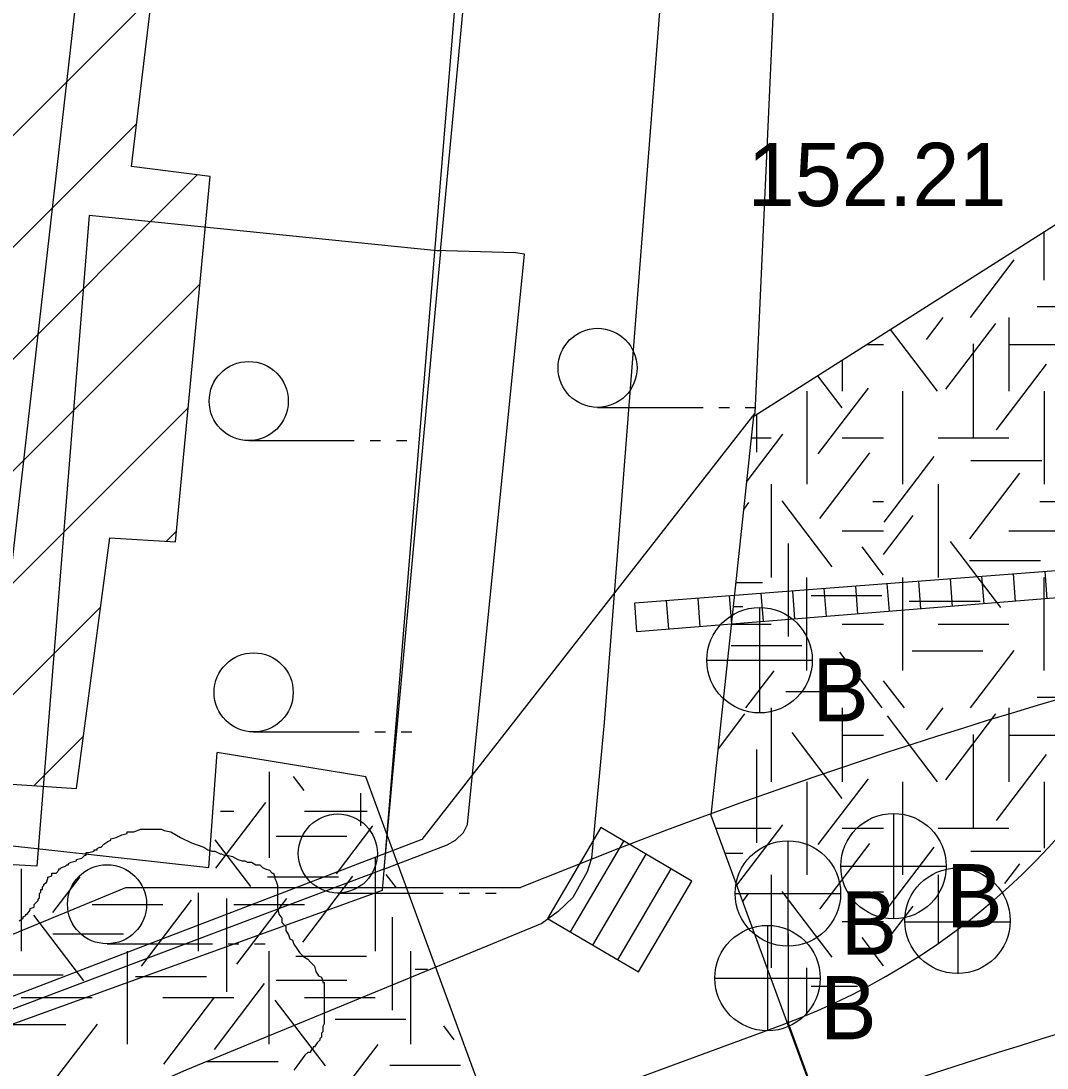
# Model space of a CAD drawing. Extents: x 419101 to 420177, y 4451541 to 4452254.
# Drawn here: x 419828.86 to 419848.32, y 4451830.95 to 4451850.82 of the extents above; entities that cross this region are included whole.
import ezdxf

# ---------------------------------------------------------------- set-up
doc = ezdxf.new("R2010")
doc.units = 0
for name, color, linetype in [('2_KADASTRO', 7, 'Continuous'), ('3_HALİHAZIR', 7, 'Continuous'), ('Level 10', 7, 'Continuous'), ('Level 3', 7, 'Continuous'), ('Level 41', 7, 'Continuous'), ('Level 60', 7, 'Continuous'), ('Level 62', 7, 'Continuous')]:
    doc.layers.add(name, color=color, linetype=linetype)

msp = doc.modelspace()

# ---------------------------------------------------------------- linework, layer by layer
at = {"layer": '2_KADASTRO'}
msp.add_lwpolyline([(419797.492, 4451855.675), (419798.065, 4451861.346), (419799.155, 4451872.13), (419838.56, 4451869.237), (419837.11, 4451851.442), (419836.727, 4451846.749), (419835.711, 4451834.324), (419821.984, 4451829.361), (419818.491, 4451828.088), (419798.137, 4451820.727)], close=True, dxfattribs=at)
at = {"layer": '3_HALİHAZIR'}
for p, q in [((419824.534, 4451844.473), (419831.34, 4451851.279)), ((419817.894, 4451835.712), (419831.054, 4451848.872)), ((419819.841, 4451835.537), (419832.201, 4451847.898)), ((419821.788, 4451835.363), (419832.255, 4451845.83)), ((419823.735, 4451835.188), (419832.033, 4451843.487)), ((419839.794, 4451843.486), (419841.794, 4451843.486)), ((419842.094, 4451843.486), (419842.294, 4451843.486)), ((419842.594, 4451843.486), (419842.794, 4451843.486)), ((419833.178, 4451842.856), (419835.178, 4451842.856)), ((419835.478, 4451842.856), (419835.678, 4451842.856)), ((419835.978, 4451842.856), (419836.178, 4451842.856)), ((419831.616, 4451840.948), (419831.811, 4451841.143)), ((419847.676, 4451840.327), (419847.716, 4451839.807)), ((419848.275, 4451840.373), (419848.314, 4451839.855)), ((419845.283, 4451840.144), (419845.324, 4451839.615)), ((419845.882, 4451840.19), (419845.922, 4451839.663)), ((419846.48, 4451840.236), (419846.52, 4451839.711)), ((419847.078, 4451840.282), (419847.118, 4451839.759)), ((419842.89, 4451839.961), (419842.932, 4451839.422)), ((419843.489, 4451840.007), (419843.53, 4451839.47)), ((419844.087, 4451840.052), (419844.128, 4451839.519)), ((419844.685, 4451840.098), (419844.726, 4451839.567)), ((419841.096, 4451839.823), (419841.137, 4451839.278)), ((419841.694, 4451839.869), (419841.736, 4451839.326)), ((419842.292, 4451839.915), (419842.334, 4451839.374)), ((419827.112, 4451836.445), (419830.37, 4451839.702)), ((419842.867, 4451839.69), (419842.867, 4451837.69)), ((419841.867, 4451838.69), (419843.867, 4451838.69)), ((419829.099, 4451836.31), (419830.041, 4451837.252)), ((419833.271, 4451837.33), (419835.271, 4451837.33)), ((419835.571, 4451837.33), (419835.771, 4451837.33)), ((419836.071, 4451837.33), (419836.271, 4451837.33)), ((419845.407, 4451835.783), (419845.407, 4451833.783)), ((419839.857, 4451835.515), (419838.844, 4451833.791)), ((419839.857, 4451835.515), (419838.844, 4451833.791)), ((419841.581, 4451834.502), (419839.857, 4451835.515)), ((419841.581, 4451834.502), (419839.857, 4451835.515)), ((419839.279, 4451833.535), (419840.292, 4451835.26)), ((419843.404, 4451835.266), (419843.404, 4451833.266)), ((419839.706, 4451833.284), (419840.719, 4451835.009)), ((419844.407, 4451834.783), (419846.407, 4451834.783)), ((419840.178, 4451833.007), (419841.192, 4451834.731)), ((419846.636, 4451832.74), (419846.636, 4451834.74)), ((419840.568, 4451832.778), (419841.581, 4451834.502)), ((419840.568, 4451832.778), (419841.581, 4451834.502)), ((419834.868, 4451834.274), (419836.868, 4451834.274)), ((419837.168, 4451834.274), (419837.368, 4451834.274)), ((419837.668, 4451834.274), (419837.868, 4451834.274)), ((419842.404, 4451834.266), (419844.404, 4451834.266)), ((419838.844, 4451833.791), (419840.568, 4451832.778)), ((419838.844, 4451833.791), (419840.568, 4451832.778)), ((419843.017, 4451833.661), (419843.017, 4451831.661)), ((419845.616, 4451833.73), (419847.616, 4451833.73)), ((419830.49, 4451833.311), (419832.49, 4451833.311)), ((419832.79, 4451833.311), (419832.99, 4451833.311)), ((419833.29, 4451833.311), (419833.49, 4451833.311)), ((419842.017, 4451832.661), (419844.017, 4451832.661))]:
    msp.add_line(p, q, dxfattribs=at)
for points in [[(419803.705, 4451853.541), (419803.094, 4451846.379), (419801.617, 4451846.462), (419800.912, 4451838.831), (419802.392, 4451838.591), (419801.958, 4451833.65), (419805.823, 4451833.166), (419805.704, 4451831.876), (419812.088, 4451831.235), (419812.306, 4451832.66), (419816.19, 4451832.424), (419816.618, 4451837.226), (419817.403, 4451837.21), (419817.369, 4451835.759), (419825.037, 4451835.071), (419825.286, 4451836.569), (419829.908, 4451836.255), (419830.545, 4451841.011), (419831.791, 4451840.938), (419832.448, 4451847.867), (419830.957, 4451848.053), (419831.347, 4451851.339)], [(419836.817, 4451846.452), (419837.348, 4451852.133)], [(419841.024, 4451851.727), (419839.922, 4451837.507), (419839.676, 4451834.933), (419839.599, 4451834.673), (419839.324, 4451834.19), (419839.045, 4451833.925), (419838.738, 4451833.693), (419831.983, 4451830.915), (419822.667, 4451826.822)], [(419836.817, 4451846.452), (419830.148, 4451847.127), (419829.16, 4451834.781), (419822.436, 4451835.166), (419822.134, 4451829.599)], [(419836.817, 4451846.452), (419835.738, 4451834.729), (419822.093, 4451829.583)], [(419835.738, 4451834.729), (419836.944, 4451835.189), (419837.098, 4451835.277), (419837.254, 4451835.42), (419837.327, 4451835.573), (419838.41, 4451846.393), (419838.237, 4451846.42), (419836.693, 4451846.465)]]:
    msp.add_lwpolyline(points, dxfattribs=at)
msp.add_lwpolyline([(419840.539, 4451839.23), (419840.498, 4451839.777), (419851.208, 4451840.598), (419851.255, 4451840.092)], close=True, dxfattribs=at)
for centre, radius in [((419839.794, 4451844.236), 0.75), ((419833.178, 4451843.606), 0.75), ((419842.867, 4451838.69), 1), ((419833.271, 4451838.08), 0.75), ((419834.868, 4451835.024), 0.75), ((419845.407, 4451834.783), 1), ((419843.404, 4451834.266), 1), ((419830.49, 4451834.061), 0.75), ((419846.621, 4451833.748), 1), ((419843.017, 4451832.661), 1)]:
    msp.add_circle(centre, radius, dxfattribs=at)
at = {"layer": 'Level 10'}
msp.add_lwpolyline([(419794.315, 4451890.489), (419840.672, 4451887.325), (419843.481, 4451858.847), (419842.779, 4451843.378), (419836.458, 4451835.291), (419798.881, 4451820.877), (419792.208, 4451851.112), (419791.857, 4451872.559)], close=True, dxfattribs=at)
at = {"layer": 'Level 3'}
for points in [[(419830.664, 4451835.328), (419830.768, 4451835.38), (419830.871, 4451835.406), (419830.871, 4451835.432), (419830.897, 4451835.432), (419830.923, 4451835.432), (419831.001, 4451835.432), (419831.131, 4451835.484), (419831.235, 4451835.484), (419831.312, 4451835.484), (419831.364, 4451835.484), (419831.442, 4451835.484), (419831.494, 4451835.484), (419831.52, 4451835.484), (419831.572, 4451835.458), (419831.702, 4451835.432), (419831.883, 4451835.328), (419832.091, 4451835.224), (419832.324, 4451835.146), (419832.402, 4451835.094), (419832.48, 4451835.068), (419832.532, 4451835.068), (419832.584, 4451835.042), (419832.635, 4451835.016), (419832.661, 4451835.016), (419832.713, 4451834.99), (419832.765, 4451834.99), (419832.869, 4451834.964), (419832.973, 4451834.912), (419833.05, 4451834.886), (419833.102, 4451834.886), (419833.154, 4451834.86), (419833.206, 4451834.86), (419833.232, 4451834.86), (419833.31, 4451834.809), (419833.388, 4451834.809), (419833.44, 4451834.757), (419833.491, 4451834.731), (419833.569, 4451834.705), (419833.621, 4451834.653), (419833.647, 4451834.653), (419833.673, 4451834.575), (419833.673, 4451834.549), (419833.699, 4451834.497), (419833.725, 4451834.419), (419833.725, 4451834.393), (419833.725, 4451834.315), (419833.725, 4451834.263), (419833.725, 4451834.185), (419833.725, 4451834.159), (419833.725, 4451834.081), (419833.725, 4451834.004), (419833.751, 4451833.874), (419833.803, 4451833.796), (419833.803, 4451833.718), (419833.881, 4451833.64), (419833.881, 4451833.562), (419833.932, 4451833.484), (419833.958, 4451833.406), (419834.01, 4451833.38), (419834.036, 4451833.302), (419834.088, 4451833.224), (419834.14, 4451833.147), (419834.218, 4451833.069), (419834.296, 4451833.017), (419834.347, 4451832.965), (419834.373, 4451832.939), (419834.425, 4451832.887), (419834.451, 4451832.783), (419834.503, 4451832.705), (419834.555, 4451832.679), (419834.581, 4451832.601), (419834.581, 4451832.575), (419834.607, 4451832.575), (419834.607, 4451832.549), (419834.607, 4451832.523), (419834.607, 4451832.471), (419834.607, 4451832.368), (419834.607, 4451832.316), (419834.607, 4451832.238), (419834.607, 4451832.16), (419834.607, 4451832.082), (419834.607, 4451832.004), (419834.607, 4451831.926), (419834.607, 4451831.874), (419834.607, 4451831.796), (419834.581, 4451831.744), (419834.581, 4451831.64), (419834.555, 4451831.614), (419834.555, 4451831.537), (419834.529, 4451831.511), (419834.529, 4451831.485), (419834.477, 4451831.433), (419834.425, 4451831.355), (419834.399, 4451831.355), (419834.399, 4451831.329), (419834.373, 4451831.303), (419834.347, 4451831.277), (419834.347, 4451831.251), (419834.322, 4451831.251), (419834.296, 4451831.251)], [(419828.822, 4451833.744), (419828.9, 4451833.796), (419828.9, 4451833.822), (419828.952, 4451833.848), (419828.952, 4451833.874), (419828.978, 4451833.874), (419829.03, 4451833.952), (419829.03, 4451833.978), (419829.107, 4451834.004), (419829.107, 4451834.029), (419829.107, 4451834.055), (419829.159, 4451834.107), (419829.185, 4451834.133), (419829.185, 4451834.159), (419829.211, 4451834.185), (419829.211, 4451834.211), (419829.211, 4451834.237), (419829.211, 4451834.263), (419829.237, 4451834.289), (419829.237, 4451834.315), (419829.237, 4451834.341), (419829.263, 4451834.341), (419829.263, 4451834.367), (419829.263, 4451834.393), (419829.289, 4451834.419), (419829.289, 4451834.445), (419829.341, 4451834.471), (419829.367, 4451834.549), (419829.367, 4451834.575), (419829.445, 4451834.601), (419829.445, 4451834.627), (419829.445, 4451834.653), (419829.522, 4451834.653), (419829.574, 4451834.705), (419829.574, 4451834.731), (419829.6, 4451834.731), (419829.626, 4451834.757), (419829.704, 4451834.783), (419829.73, 4451834.809), (419829.756, 4451834.809), (419829.756, 4451834.835), (419829.808, 4451834.86), (419829.912, 4451834.886), (419829.912, 4451834.912), (419830.015, 4451834.938), (419830.067, 4451834.99), (419830.093, 4451834.99), (419830.093, 4451835.016), (419830.093, 4451835.042), (419830.145, 4451835.042), (419830.249, 4451835.068), (419830.249, 4451835.094), (419830.275, 4451835.094), (419830.301, 4451835.094), (419830.301, 4451835.12), (419830.353, 4451835.146), (419830.379, 4451835.146), (419830.43, 4451835.198), (419830.508, 4451835.25), (419830.56, 4451835.276), (419830.56, 4451835.302), (419830.664, 4451835.328)], [(419834.296, 4451831.251), (419834.244, 4451831.199), (419834.088, 4451830.991), (419834.036, 4451830.913)]]:
    msp.add_lwpolyline(points, dxfattribs=at)
at = {"layer": 'Level 41'}
for p, q in [((419848.268, 4451845.902), (419848.268, 4451846.82)), ((419846.867, 4451845.193), (419847.696, 4451846.284)), ((419848.129, 4451845.399), (419849.472, 4451845.399)), ((419846.03, 4451844.776), (419846.347, 4451845.193)), ((419847.596, 4451845.193), (419847.596, 4451843.795)), ((419846.241, 4451843.795), (419845.352, 4451844.965)), ((419846.401, 4451843.83), (419847.35, 4451845.08)), ((419844.902, 4451844.679), (419845.22, 4451844.679)), ((419846.921, 4451844.691), (419846.921, 4451842.924)), ((419847.596, 4451844.679), (419848.939, 4451844.679)), ((419844.432, 4451844.38), (419844.432, 4451843.795)), ((419844.432, 4451844.38), (419844.432, 4451843.795)), ((419847.361, 4451843.058), (419848.31, 4451844.308)), ((419844.433, 4451843.479), (419843.971, 4451844.087)), ((419843.761, 4451843.795), (419843.761, 4451842.028)), ((419843.761, 4451843.795), (419843.761, 4451842.028)), ((419843.981, 4451842.602), (419844.93, 4451843.852)), ((419845.582, 4451842.028), (419845.582, 4451843.795)), ((419848.268, 4451843.795), (419848.268, 4451842.028)), ((419842.807, 4451843.346), (419842.807, 4451842.638)), ((419842.629, 4451842.087), (419843.305, 4451842.977)), ((419842.717, 4451842.911), (419843.089, 4451842.911)), ((419844.432, 4451842.911), (419845.22, 4451842.911)), ((419846.253, 4451842.911), (419847.596, 4451842.911)), ((419844.007, 4451841.376), (419844.957, 4451842.625)), ((419845.23, 4451841.307), (419846.179, 4451842.556)), ((419846.877, 4451842.477), (419848.22, 4451842.477)), ((419846.855, 4451840.99), (419847.804, 4451842.24)), ((419843.089, 4451842.028), (419843.089, 4451840.261)), ((419846.253, 4451842.028), (419846.253, 4451840.261)), ((419844.246, 4451840.464), (419843.297, 4451841.713)), ((419842.572, 4451841.557), (419842.666, 4451841.68)), ((419845.016, 4451841.704), (419845.22, 4451841.704)), ((419848.183, 4451841.704), (419849.526, 4451841.704)), ((419845.22, 4451840.698), (419845.779, 4451841.434)), ((419844.432, 4451841.144), (419845.22, 4451841.144)), ((419847.596, 4451841.144), (419848.939, 4451841.144)), ((419847.44, 4451839.693), (419846.491, 4451840.943)), ((419843.407, 4451840.906), (419843.407, 4451839.138)), ((419845.22, 4451840.304), (419844.814, 4451840.838)), ((419846.85, 4451840.584), (419848.193, 4451840.584)), ((419842.423, 4451840.163), (419842.923, 4451840.163)), ((419843.761, 4451838.493), (419843.761, 4451840.261)), ((419845.582, 4451838.493), (419845.582, 4451840.261)), ((419848.268, 4451838.493), (419848.268, 4451840.261)), ((419843.843, 4451839.918), (419845.186, 4451839.918)), ((419845.705, 4451839.812), (419847.048, 4451839.812)), ((419842.374, 4451839.707), (419842.549, 4451839.707)), ((419842.338, 4451839.377), (419843.089, 4451839.377)), ((419844.432, 4451839.377), (419845.22, 4451839.377)), ((419846.253, 4451839.377), (419847.596, 4451839.377)), ((419842.325, 4451838.97), (419843.668, 4451838.97)), ((419845.191, 4451837.784), (419844.389, 4451838.84)), ((419845.759, 4451838.866), (419847.101, 4451838.866)), ((419846.867, 4451837.784), (419847.696, 4451838.875)), ((419842.608, 4451837.784), (419843.145, 4451838.49)), ((419845.614, 4451837.784), (419845.22, 4451838.302)), ((419843.364, 4451838.096), (419844.707, 4451838.096)), ((419848.129, 4451837.99), (419849.472, 4451837.99)), ((419843.089, 4451837.784), (419843.089, 4451836.386)), ((419844.432, 4451837.784), (419844.432, 4451836.386)), ((419844.432, 4451837.784), (419844.432, 4451836.386)), ((419846.03, 4451837.367), (419846.347, 4451837.784)), ((419847.596, 4451837.784), (419847.596, 4451836.386)), ((419842.085, 4451837.012), (419842.585, 4451837.671)), ((419846.241, 4451836.386), (419845.292, 4451837.636)), ((419846.401, 4451836.421), (419847.35, 4451837.671)), ((419844.433, 4451836.07), (419843.484, 4451837.319)), ((419844.432, 4451837.27), (419845.22, 4451837.27)), ((419846.921, 4451837.282), (419846.921, 4451835.515)), ((419847.596, 4451837.27), (419848.939, 4451837.27)), ((419842.807, 4451836.996), (419842.807, 4451835.229)), ((419847.361, 4451835.649), (419848.31, 4451836.899)), ((419833.564, 4451836.571), (419833.564, 4451834.941)), ((419834.232, 4451836.217), (419834.029, 4451836.484)), ((419843.761, 4451836.386), (419843.761, 4451834.619)), ((419843.761, 4451836.386), (419843.761, 4451834.619)), ((419843.981, 4451835.193), (419844.93, 4451836.443)), ((419845.582, 4451834.619), (419845.582, 4451836.386)), ((419848.268, 4451836.386), (419848.268, 4451835.125)), ((419835.296, 4451836.166), (419835.296, 4451835.551)), ((419832.554, 4451834.745), (419833.505, 4451835.994)), ((419832.645, 4451835.824), (419832.892, 4451835.824)), ((419834.235, 4451835.824), (419835.426, 4451835.824)), ((419842.435, 4451834.422), (419843.305, 4451835.568)), ((419834.845, 4451834.64), (419835.532, 4451835.546)), ((419842.039, 4451835.502), (419843.089, 4451835.502)), ((419844.432, 4451835.502), (419845.22, 4451835.502)), ((419846.253, 4451835.502), (419847.596, 4451835.502)), ((419833.22, 4451834.395), (419832.544, 4451835.284)), ((419833.695, 4451835.354), (419835.038, 4451835.354)), ((419844.007, 4451833.967), (419844.957, 4451835.216)), ((419842.211, 4451835.032), (419842.549, 4451835.032)), ((419845.23, 4451833.898), (419846.179, 4451835.147)), ((419846.877, 4451835.068), (419848.204, 4451835.068)), ((419835.578, 4451834.941), (419835.578, 4451833.174)), ((419847.518, 4451834.454), (419847.804, 4451834.831)), ((419828.863, 4451834.731), (419828.863, 4451833.174)), ((419829.465, 4451833.903), (419829.98, 4451834.581)), ((419833.535, 4451834.584), (419834.878, 4451834.584)), ((419834.205, 4451833.343), (419835.155, 4451834.593)), ((419835.98, 4451834.371), (419835.786, 4451834.626)), ((419843.089, 4451834.619), (419843.089, 4451832.852)), ((419846.253, 4451834.619), (419846.253, 4451833.322)), ((419832.221, 4451834.279), (419832.221, 4451833.174)), ((419832.753, 4451834.169), (419832.753, 4451832.401)), ((419832.953, 4451832.923), (419833.902, 4451834.172)), ((419842.547, 4451834.115), (419842.666, 4451834.271)), ((419844.246, 4451833.055), (419843.297, 4451834.304)), ((419845.016, 4451834.295), (419845.22, 4451834.295)), ((419830.206, 4451834.057), (419831.549, 4451834.057)), ((419831.142, 4451832.887), (419832.092, 4451834.137)), ((419832.892, 4451834.057), (419834.235, 4451834.057)), ((419845.22, 4451833.289), (419845.779, 4451834.025)), ((419830.05, 4451832.606), (419829.101, 4451833.856)), ((419835.896, 4451833.819), (419835.896, 4451832.051)), ((419844.432, 4451833.735), (419845.22, 4451833.735)), ((419829.46, 4451833.497), (419830.803, 4451833.497)), ((419843.407, 4451833.497), (419843.407, 4451831.818)), ((419845.22, 4451832.895), (419844.814, 4451833.429)), ((419830.878, 4451831.406), (419830.878, 4451833.174)), ((419833.564, 4451831.406), (419833.564, 4451833.174)), ((419836.25, 4451831.406), (419836.25, 4451833.174)), ((419834.069, 4451833.076), (419835.412, 4451833.076)), ((419836.332, 4451832.831), (419836.567, 4451832.831)), ((419843.761, 4451832.004), (419843.761, 4451832.852)), ((419828.315, 4451832.725), (419829.658, 4451832.725)), ((419831.032, 4451832.691), (419832.375, 4451832.691)), ((419833.695, 4451832.62), (419835.038, 4451832.62)), ((419832.528, 4451831.309), (419833.477, 4451832.559)), ((419843.843, 4451832.509), (419844.723, 4451832.509)), ((419828.863, 4451832.29), (419830.206, 4451832.29)), ((419831.549, 4451832.29), (419832.892, 4451832.29)), ((419831.568, 4451831.03), (419832.517, 4451832.279)), ((419834.631, 4451830.995), (419833.681, 4451832.244)), ((419834.235, 4451832.29), (419835.578, 4451832.29)), ((419829.477, 4451830.697), (419830.306, 4451831.788)), ((419834.814, 4451831.883), (419836.157, 4451831.883)), ((419828.369, 4451831.779), (419829.711, 4451831.779)), ((419837.077, 4451831.491), (419836.878, 4451831.753)), ((419835.097, 4451830.697), (419835.634, 4451831.403)), ((419832.391, 4451831.078), (419833.734, 4451831.078)), ((419835.853, 4451831.009), (419837.196, 4451831.009))]:
    msp.add_line(p, q, dxfattribs=at)
at = {"layer": 'Level 60'}
for p, q in [((419796.917, 4451820.429), (419830.847, 4451834.376)), ((419830.847, 4451834.376), (419838.334, 4451834.376))]:
    msp.add_line(p, q, dxfattribs=at)
msp.add_lwpolyline([(419805.835, 4451866.735), (419803.007, 4451841.28), (419828.438, 4451838.361), (419831.357, 4451864.001), (419805.835, 4451866.735)], dxfattribs=at)
for centre, radius, start, end in [((419877.418, 4451739.094), 102.987, 94.68984, 112.30253), ((419876.549, 4451739.049), 96.699, 94.2053, 110.62966)]:
    msp.add_arc(centre, radius, start, end, dxfattribs=at)
at = {"layer": 'Level 62'}
for p, q in [((419842.761, 4451843.317), (419863.675, 4451856.621)), ((419841.949, 4451835.746), (419842.761, 4451843.317)), ((419810.857, 4451837.126), (419832.418, 4451834.759)), ((419832.418, 4451834.759), (419832.576, 4451836.94)), ((419832.418, 4451834.759), (419832.576, 4451836.94)), ((419832.418, 4451834.759), (419832.576, 4451836.94)), ((419835.397, 4451836.48), (419832.576, 4451836.94)), ((419838.315, 4451828.531), (419835.397, 4451836.48)), ((419843.858, 4451830.545), (419841.949, 4451835.746)), ((419847.041, 4451821.921), (419843.401, 4451831.835)), ((419847.041, 4451821.921), (419843.401, 4451831.835)), ((419847.041, 4451821.921), (419843.401, 4451831.835)), ((419800.177, 4451815.945), (419843.295, 4451831.774))]:
    msp.add_line(p, q, dxfattribs=at)
msp.add_arc((419838.814, 4451843.978), 13, 290.1603, 31.867, dxfattribs=at)

# ---------------------------------------------------------------- texts
at = {"layer": '3_HALİHAZIR'}
msp.add_text('152.21 ', height=1.2, rotation=359.9971, dxfattribs=at).set_placement((419842.641, 4451847.304))
for p in [(419843.867, 4451837.529), (419846.407, 4451833.622), (419844.404, 4451833.105), (419844.017, 4451831.5)]:
    msp.add_text('B', height=1.2, dxfattribs=at).set_placement(p)

doc.saveas('drawing.dxf')
